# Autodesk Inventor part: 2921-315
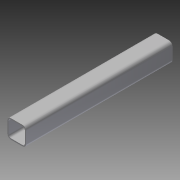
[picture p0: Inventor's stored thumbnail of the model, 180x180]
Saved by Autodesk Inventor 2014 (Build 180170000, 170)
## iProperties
Company: NHTSA/VRTC
Created: 2011-11
Part Number: 2921-315
Material: Steel
Document SubType Name: Modeling
Designer: Mike Vanvoorhis
Density: 7.85 g/cm^3
Project: CHILD SIDE IMPACT SLED
Mass: 1761.38 g
Surface Area: 1424.63 cm^2
Volume: 224.38 cm^3
Stock Number: T.S. 2" x 2" x 1/8" x 400.1mm (15.75")
Description: BENCH UPPER BELT MTG. TUBE
Appearance: Steel
Author: Dave Walker
Title: Bench Upper Belt Mounting Tube
Subject: Child Side Impact Sled
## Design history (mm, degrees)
node "Sketch1"
node "2921-2011"
node "2921-201"
node "Base1"
